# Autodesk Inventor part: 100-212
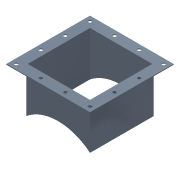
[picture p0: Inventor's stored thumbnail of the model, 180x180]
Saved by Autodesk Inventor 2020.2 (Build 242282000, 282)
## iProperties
Created: 2011-01
Part Number: 100-212
Document SubType Name: Modeling
Designer: F.Stasiak
Density: 1 g/cm^3
Material: Ogólny
Appearance: Stalowoniebieska
Company: Fabian Stasiak CAD Consulting
Manager: www.cadconsulting.pl
Author: F.Stasiak
Subject: Zbiór ćwiczeń. Autodesk Inventor 2020. Kurs podstawowy
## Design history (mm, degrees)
sketch "Szkic1"
  geometry: L1 (125, -125)-(-125, -125); L2 (-125, -125)-(-125, 125); L3 (-125, 125)-(125, 125); L4 (125, 125)-(125, -125); L5 (128, -128)-(-128, -128); L6 (-128, -128)-(-128, 128); L7 (-128, 128)-(128, 128); L8 (128, 128)-(128, -128); 3 further points
  constraints: 16 end point, 4 parallel, 2 midpoint, 2 perpendicular, 1 horizontal, 1 horizontal alignment, 1 vertical alignment, 3 other
  dimensions: "d0" = 250 distance of L2.end L3.end; "d1" = 250 distance of L1.end L2.end; "d2" = 3 distance between parallel lines of L8 L4
extrude "Wyciągnięcie proste1" new body sketch "Szkic1" distance "d3" = 200; taper "d4" = 0 deg
sketch "Szkic2"
  geometry: L1 (-125, -125)-(-125, 125) reference; L2 (-125, 125)-(125, 125) reference; L3 (125, 125)-(125, -125) reference; L4 (125, -125)-(-125, -125) reference; L5 (-128, -128)-(-128, 128) reference; L6 (128, -128)-(-128, -128) reference; L7 (128, 128)-(128, -128) reference; L8 (-128, 128)-(128, 128) reference; L9 (-168, 168)-(-168, -168); L10 (-168, -168)-(168, -168); L11 (168, -168)-(168, 168); L12 (168, 168)-(-168, 168); 1 further point
  constraints: 8 end point, 3 other
  dimensions: "d5" = 40 distance between parallel lines of L9 L5
extrude "Wyciągnięcie proste2" join sketch "Szkic2" distance "d6" = 3; taper "d7" = 0 deg
sketch "Szkic3"
  geometry: L1 (168, -168)-(168, 168) reference; L2 (-168, -168)-(168, -168) reference; L3 (-168, 168)-(-168, -168) reference; L4 (168, 168)-(-168, 168) reference; L5 (148, -148)-(148, 148); L6 (148, 148)-(-148, 148); L7 (-148, 148)-(-148, -148); L8 (-148, -148)-(148, -148); 1 further point
  constraints: 8 end point, 3 other
  dimensions: "d8" = 20 distance between parallel lines of L1 L5
hole "Hole2" sketch "Szkic3" diameter "d16" = 13; stored, may be unused: countersink angle "d20" = 90 deg, drill point angle "d22" = 118 deg; dims "d17" = 6, "d18" = 4, "d19" = 2, "d21" = 8
pattern_linear "Szyk prostokątny1"
sketch "Szkic4"
  geometry: L1 (0, 0)-(256, 0) reference; C1 r 200 at (128, 135); 2 further points
  constraints: 1 centre point, 1 midpoint, 1 vertical alignment
  dimensions: "d25" = 400 diameter of C1; "d26" = 135 distance from line of L1 C1.centre
extrude "Wyciągnięcie proste3" cut sketch "Szkic4" extent not by distance; stored distance "d27" = 0; taper "d28" = 0 deg
node "Bryła1"
node "Pętla rzutowana1"
